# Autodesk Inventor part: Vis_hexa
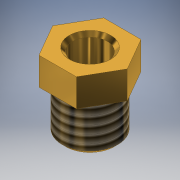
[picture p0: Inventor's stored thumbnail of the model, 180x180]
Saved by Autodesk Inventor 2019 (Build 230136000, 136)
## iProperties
Created: 2018-06
Part Number: Vis_hexa
Material: Laiton, jaune doux
Document SubType Name: Modeling
Designer: Fabian Perrée
Density: 8.47 g/cm^3
Appearance: Laiton - Satiné
Author: Fabian Perrée
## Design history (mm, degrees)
sketch "Esquisse1"
  geometry: C1 r 6 at (0, 0); C2 r 3.75 at (0, 0); 1 further point
  constraints: 2 centre point, 2 coincident
  dimensions: "d0" = 12 diameter of C1; "d1" = 7.5 diameter of C2
extrude "Extrusion1" new body sketch "Esquisse1" distance "d2" = 16; taper "d3" = 0 deg
sketch "Esquisse2"
  geometry: L1 (4.041, -7)-(-4.041, -7); L2 (-4.041, -7)-(-8.083, 0); L3 (-8.083, 0)-(-4.041, 7); L4 (-4.041, 7)-(4.041, 7); L5 (4.041, 7)-(8.083, 0); L6 (8.083, 0)-(4.041, -7); C1 r 3.75 at (0, 0) reference; C2 r 6 at (0, 0) reference; 1 further point
  constraints: 12 end point, 1 coincident, 1 horizontal, 13 other
  dimensions: "d4" = 14 distance between parallel lines of L4 L1
extrude "Extrusion2" join sketch "Esquisse2" distance "d5" = 6; taper "d6" = 0 deg
chamfer "Chanfrein1" distance "d7" = 0.75; stored, may be unused: second distance "d8" = 2, angle "d9" = 45 deg
feature "Filetage1" dims "d10" = 10, "d11" = 0
node "Solide1"
